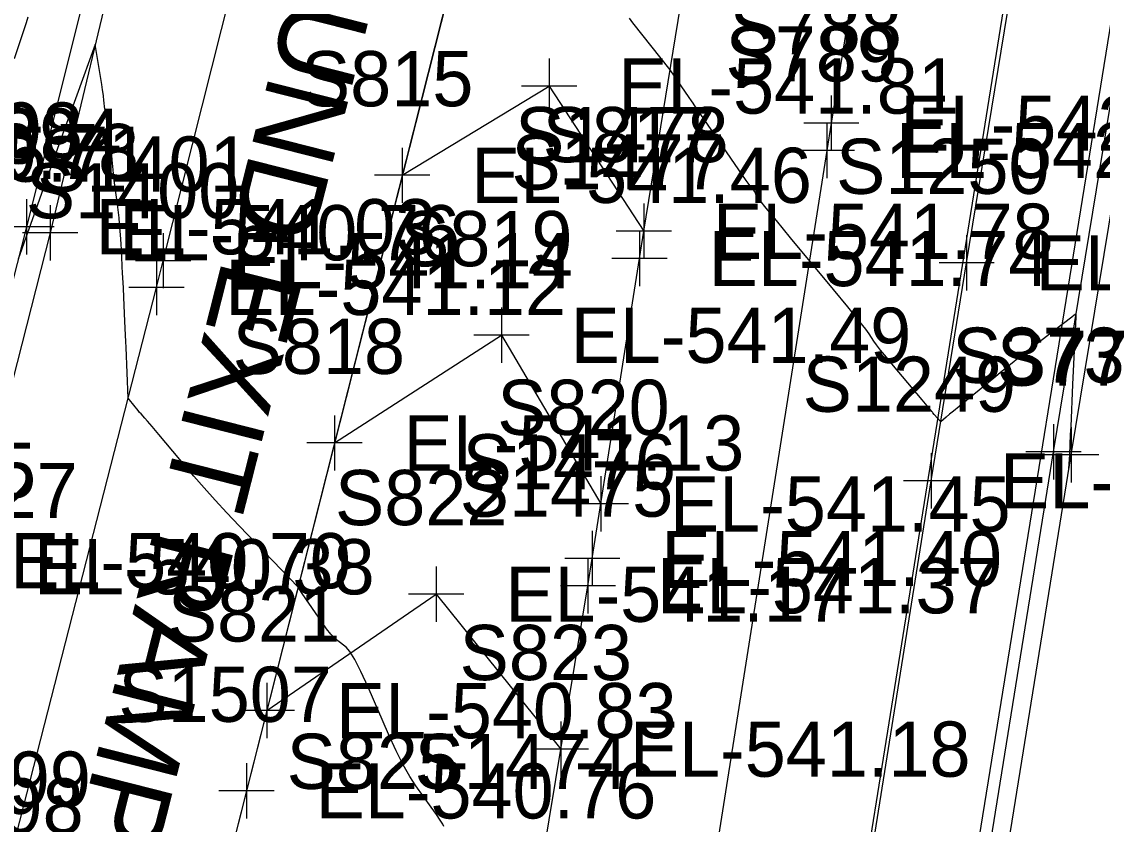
# Model space of a CAD drawing. Extents: x 1724534 to 1727318, y 657156 to 660047.
# Drawn here: x 1725578 to 1725656.3, y 659496.3 to 659554.5 of the extents above; entities that cross this region are included whole.
import ezdxf

# ---------------------------------------------------------------- set-up
doc = ezdxf.new("R2010")
doc.units = 0
for name, color, linetype in [('SURVEY - CENTERLINE - Preliminary', 7, 'Continuous'), ('SURVEY - CONTOURS - Intermediate with optional Text', 7, 'Continuous'), ('SURVEY - DRAINAGE - Area Shapes', 7, 'Continuous'), ('SURVEY - DRAINAGE - Storm Sewer', 7, 'Continuous'), ('SURVEY - DTM - Breaklines', 7, 'Continuous'), ('SURVEY - DTM - Breaklines - Points - Elevations', 7, 'Continuous'), ('SURVEY - DTM - Breaklines - Points - Locators', 7, 'Continuous'), ('SURVEY - DTM - Breaklines - Points - Numbers', 7, 'Continuous'), ('SURVEY - NON-TRANSPORTATION - Features - Points - Elevations', 7, 'Continuous'), ('SURVEY - TRAFFIC CONTROL - Pavement Marking - Points - Elevations', 7, 'Continuous'), ('SURVEY - TRAFFIC CONTROL - Pavement Marking - Points - Locators', 7, 'Continuous'), ('SURVEY - TRAFFIC CONTROL - Pavement Marking - Points - Numbers', 7, 'Continuous'), ('SURVEY - TRAFFIC CONTROL - Pavement Marking with Text', 7, 'Continuous'), ('SURVEY - TRANSPORTATION - Features', 7, 'Continuous'), ('SURVEY - TRANSPORTATION - Features - Points - Elevations', 7, 'Continuous'), ('SURVEY - TRANSPORTATION - Features - Points - Locators', 7, 'Continuous'), ('SURVEY - TRANSPORTATION - Features - Points - Numbers', 7, 'Continuous'), ('SURVEY - TRANSPORTATION - Roads', 7, 'Continuous'), ('SURVEY - TRANSPORTATION - Roads - Points - Elevations', 7, 'Continuous'), ('SURVEY - TRANSPORTATION - Roads - Points - Locators', 7, 'Continuous'), ('SURVEY - TRANSPORTATION - Roads - Points - Numbers', 7, 'Continuous'), ('SURVEY - TRANSPORTATION - Roads Text', 7, 'Continuous')]:
    doc.layers.add(name, color=color, linetype=linetype)

msp = doc.modelspace()

# ---------------------------------------------------------------- linework, layer by layer
at = {"layer": 'SURVEY - CENTERLINE - Preliminary'}
msp.add_line((1725628.749, 659634.745), (1725510.016, 659165.778), dxfattribs=at)
msp.add_line((1725628.749, 659634.745), (1725510.016, 659165.778), dxfattribs=at)
msp.add_line((1725628.749, 659634.745), (1725510.016, 659165.778), dxfattribs=at)
at = {"layer": 'SURVEY - CONTOURS - Intermediate with optional Text'}
for points in [[(1725578.479, 659554.8), (1725578.347, 659554.389), (1725577.489, 659551.776)], [(1725653.9, 659522.09), (1725653.958, 659523.08), (1725654.024, 659524.558), (1725654.049, 659525.135), (1725654.184, 659528.189), (1725654.412, 659533.086), (1725654.423, 659533.317), (1725654.333, 659533.251), (1725654.283, 659533.213), (1725654.275, 659533.207), (1725654.097, 659533.067), (1725652.803, 659532.07), (1725650.992, 659530.675), (1725650.323, 659530.157), (1725649.676, 659529.646), (1725649.051, 659529.144), (1725648.447, 659528.651), (1725645.938, 659526.584), (1725645.53, 659526.251), (1725645.256, 659526.033), (1725645.011, 659525.829), (1725644.607, 659525.485), (1725644.136, 659526.017), (1725644.035, 659526.137), (1725644.01, 659526.171), (1725643.966, 659526.236), (1725643.878, 659526.344), (1725643.276, 659527.064), (1725641.199, 659529.528), (1725640.671, 659530.162), (1725640.257, 659530.671), (1725639.958, 659531.056), (1725639.773, 659531.317), (1725639.433, 659531.849), (1725639.175, 659532.199), (1725638.658, 659532.852), (1725637.881, 659533.806), (1725636.844, 659535.063), (1725633.732, 659538.816), (1725632.706, 659540.057), (1725631.963, 659540.965), (1725631.502, 659541.54), (1725631.324, 659541.782), (1725631.225, 659541.982), (1725631.185, 659542.057), (1725631.138, 659542.133), (1725631.085, 659542.211), (1725631.026, 659542.288), (1725630.859, 659542.497), (1725630.779, 659542.602), (1725630.664, 659542.762), (1725630.513, 659542.976), (1725627.182, 659547.818), (1725626.748, 659548.452), (1725626.665, 659548.576), (1725626.563, 659548.735), (1725626.395, 659548.983), (1725625.008, 659550.977), (1725622.31, 659554.396), (1725622.066, 659554.733)], [(1725608.605, 659496.159), (1725608.527, 659496.337), (1725608.351, 659496.63), (1725608.076, 659497.039), (1725607.702, 659497.564), (1725606.575, 659499.117), (1725606.135, 659499.787), (1725605.661, 659500.632), (1725605.152, 659501.651), (1725604.609, 659502.846), (1725603.116, 659506.264), (1725602.597, 659507.406), (1725602.162, 659508.27), (1725601.809, 659508.855), (1725601.54, 659509.161), (1725600.932, 659509.605), (1725600.69, 659509.814), (1725600.42, 659510.106), (1725600.12, 659510.482), (1725599.792, 659510.942), (1725598.354, 659513.049), (1725598.046, 659513.5), (1725593.771, 659517.948), (1725592.88, 659518.888), (1725592.039, 659519.802), (1725591.248, 659520.69), (1725590.506, 659521.552), (1725587.956, 659524.572), (1725587.469, 659525.145), (1725587.135, 659525.536), (1725586.954, 659525.743), (1725586.675, 659526.051), (1725586.57, 659526.169), (1725586.463, 659526.293), (1725586.355, 659526.423), (1725586.246, 659526.559), (1725585.733, 659527.205), (1725585.592, 659530.859), (1725585.571, 659531.312), (1725585.546, 659531.752), (1725585.501, 659532.764), (1725585.429, 659534.477), (1725585.395, 659535.179), (1725585.329, 659536.264), (1725585.309, 659536.701), (1725585.286, 659537.477), (1725585.276, 659537.714), (1725585.26, 659538.001), (1725585.237, 659538.34), (1725585.207, 659538.73), (1725585.117, 659539.838), (1725585.081, 659540.249), (1725585.04, 659540.65), (1725584.994, 659541.042), (1725584.944, 659541.425), (1725584.803, 659542.432), (1725584.754, 659542.797), (1725584.711, 659543.136), (1725584.676, 659543.449), (1725584.648, 659543.735), (1725584.581, 659544.465), (1725584.55, 659544.77), (1725584.504, 659545.137), (1725584.445, 659545.568), (1725584.373, 659546.061), (1725584.09, 659547.934), (1725584.035, 659548.309), (1725583.998, 659548.583), (1725583.977, 659548.758), (1725583.943, 659549.091), (1725583.921, 659549.265), (1725583.882, 659549.538), (1725583.824, 659549.91), (1725583.351, 659552.807), (1725582.024, 659549.156), (1725580.991, 659546.29), (1725580.237, 659544.206), (1725578.776, 659540.122), (1725578.435, 659539.173), (1725577.779, 659537.276)]]:
    msp.add_lwpolyline(points, dxfattribs=at)
at = {"layer": 'SURVEY - DRAINAGE - Area Shapes'}
msp.add_lwpolyline([(1725457.865, 659006.777), (1725413.857, 659016.262), (1725297.605, 659050.843), (1725314.042, 659296.608), (1725386.76, 659493.901), (1725483.401, 659755.229), (1725623.949, 659732.704), (1725676.22, 659724.326), (1725634.82, 659466.017), (1725543.324, 659353.721), (1725499.683, 659185.923), (1725479.088, 659106.738)], close=True, dxfattribs=at)
at = {"layer": 'SURVEY - DRAINAGE - Storm Sewer'}
msp.add_line((1725684.983, 659727.993), (1725645.113, 659481.278), dxfattribs=at)
at = {"layer": 'SURVEY - DTM - Breaklines'}
for points in [[(1725623.603, 659326.195), (1725625.596, 659340.96), (1725631.474, 659380.353), (1725637.663, 659419.872), (1725643.838, 659459.39), (1725646.925, 659478.842), (1725647.706, 659483.647), (1725654.062, 659523.097), (1725660.549, 659562.561), (1725667.001, 659602.053), (1725673.284, 659641.547), (1725679.659, 659681.01), (1725686.766, 659724.695), (1725687.764, 659730.895), (1725694.149, 659770.379), (1725697.503, 659791.065)], [(1725602.477, 659636.589), (1725597.046, 659612.281), (1725591.056, 659587.95), (1725584.432, 659563.857), (1725578.377, 659539.615), (1725572.193, 659515.421), (1725566.455, 659491.037), (1725562.449, 659475.306), (1725561.076, 659469.841), (1725554.596, 659445.712), (1725548.416, 659421.487), (1725542.14, 659397.279), (1725535.913, 659373.067), (1725529.984, 659349.877), (1725523.806, 659325.59), (1725517.787, 659301.313), (1725511.183, 659275.168), (1725504.884, 659250.966), (1725498.725, 659226.793)]]:
    msp.add_lwpolyline(points, dxfattribs=at)
at = {"layer": 'SURVEY - DTM - Breaklines - Points - Locators'}
for p, q in [((1725578.377, 659541.615), (1725578.377, 659537.615)), ((1725580.377, 659539.615), (1725576.377, 659539.615)), ((1725654.062, 659525.097), (1725654.062, 659521.097)), ((1725656.062, 659523.097), (1725652.062, 659523.097))]:
    msp.add_line(p, q, dxfattribs=at)
at = {"layer": 'SURVEY - TRAFFIC CONTROL - Pavement Marking - Points - Locators'}
for p, q in [((1725616.236, 659551.808), (1725616.236, 659547.808)), ((1725618.236, 659549.808), (1725614.236, 659549.808)), ((1725636.683, 659549.114), (1725636.683, 659545.114)), ((1725638.683, 659547.114), (1725634.683, 659547.114)), ((1725636.368, 659547.139), (1725636.368, 659543.139)), ((1725605.591, 659545.34), (1725605.591, 659541.34)), ((1725638.368, 659545.139), (1725634.368, 659545.139)), ((1725607.591, 659543.34), (1725603.591, 659543.34)), ((1725623.106, 659541.288), (1725623.106, 659537.288)), ((1725625.106, 659539.288), (1725621.106, 659539.288)), ((1725612.791, 659533.753), (1725612.791, 659529.753)), ((1725614.791, 659531.753), (1725610.791, 659531.753)), ((1725600.69, 659525.951), (1725600.69, 659521.951)), ((1725602.69, 659523.951), (1725598.69, 659523.951)), ((1725619.989, 659521.534), (1725619.989, 659517.534)), ((1725621.989, 659519.534), (1725617.989, 659519.534)), ((1725608.06, 659514.995), (1725608.06, 659510.995)), ((1725610.06, 659512.995), (1725606.06, 659512.995)), ((1725595.789, 659506.563), (1725595.789, 659502.563)), ((1725597.789, 659504.563), (1725593.789, 659504.563)), ((1725617.086, 659503.771), (1725617.086, 659499.771)), ((1725619.086, 659501.771), (1725615.086, 659501.771))]:
    msp.add_line(p, q, dxfattribs=at)
at = {"layer": 'SURVEY - TRAFFIC CONTROL - Pavement Marking with Text'}
for points in [[(1725677.077, 659796.306), (1725674.763, 659781.986), (1725662.242, 659705.025), (1725649.129, 659624.102), (1725636.683, 659547.114), (1725636.368, 659545.139), (1725624.177, 659468.103), (1725623.248, 659462.175), (1725617.375, 659424.632), (1725617.069, 659422.656), (1725605.507, 659345.515), (1725605.215, 659343.536), (1725602.951, 659328.104)], [(1725605.591, 659543.34), (1725616.236, 659549.808), (1725623.106, 659539.288)], [(1725600.69, 659523.951), (1725612.791, 659531.753), (1725619.989, 659519.534)], [(1725595.789, 659504.563), (1725608.06, 659512.995), (1725617.086, 659501.771)]]:
    msp.add_lwpolyline(points, dxfattribs=at)
at = {"layer": 'SURVEY - TRANSPORTATION - Features'}
for points in [[(1725622.206, 659326.386), (1725624.286, 659341.139), (1725630.167, 659380.556), (1725636.351, 659420.075), (1725642.552, 659459.59), (1725645.64, 659479.047), (1725646.421, 659483.852), (1725652.777, 659523.307), (1725659.265, 659562.771), (1725665.716, 659602.26), (1725671.999, 659641.754), (1725678.373, 659681.219), (1725685.481, 659724.905), (1725686.48, 659731.104), (1725692.864, 659770.586), (1725696.218, 659791.273)], [(1725603.581, 659636.317), (1725598.147, 659611.998), (1725592.159, 659587.674), (1725585.904, 659563.486), (1725580.094, 659539.18), (1725573.908, 659514.982), (1725567.671, 659490.732), (1725563.666, 659475.001), (1725562.294, 659469.536), (1725556.226, 659445.299), (1725550.205, 659421.034), (1725543.929, 659396.827), (1725537.702, 659372.615), (1725531.77, 659349.415), (1725525.595, 659325.139), (1725519.577, 659300.865), (1725512.973, 659274.714), (1725506.673, 659250.514), (1725500.512, 659226.334)]]:
    msp.add_lwpolyline(points, dxfattribs=at)
at = {"layer": 'SURVEY - TRANSPORTATION - Features - Points - Locators'}
for p, q in [((1725580.094, 659541.18), (1725580.094, 659537.18)), ((1725582.094, 659539.18), (1725578.094, 659539.18)), ((1725652.777, 659525.307), (1725652.777, 659521.307)), ((1725654.777, 659523.307), (1725650.777, 659523.307))]:
    msp.add_line(p, q, dxfattribs=at)
at = {"layer": 'SURVEY - TRANSPORTATION - Roads'}
for points in [[(1725614.209, 659327.48), (1725617.731, 659353.241), (1725618.016, 659355.22), (1725622.921, 659386.843), (1725624.432, 659396.727), (1725627.753, 659418.475), (1725628.057, 659420.452), (1725635.106, 659465.907), (1725635.414, 659467.883), (1725643.908, 659521.207), (1725646.487, 659536.996), (1725655.836, 659594.229), (1725667.285, 659665.297), (1725672.1, 659694.897), (1725680.449, 659746.206), (1725687.947, 659792.609)], [(1725590.712, 659328.916), (1725598.166, 659381.246), (1725598.45, 659383.225), (1725602.437, 659408.918), (1725603.053, 659412.87), (1725607.12, 659438.551), (1725610.58, 659460.277), (1725610.891, 659462.253), (1725615.777, 659493.878), (1725619.05, 659513.608), (1725619.366, 659515.583), (1725622.791, 659537.313), (1725623.106, 659539.288), (1725628.245, 659570.869), (1725628.563, 659572.843), (1725632.342, 659596.54), (1725632.661, 659598.515), (1725636.547, 659622.193)], [(1725509.717, 659226.971), (1725517.054, 659256.051), (1725522.463, 659277.37), (1725530.246, 659308.405), (1725536.116, 659331.674), (1725536.614, 659333.611), (1725542.122, 659354.908), (1725554.364, 659403.386), (1725567.129, 659453.798), (1725567.617, 659455.737), (1725576.381, 659490.656), (1725576.873, 659492.594), (1725587.785, 659535.219), (1725588.276, 659537.157), (1725594.628, 659562.367), (1725602.882, 659595.344), (1725603.37, 659597.283), (1725609.346, 659620.521)], [(1725624.67, 659618.957), (1725609.021, 659556.912), (1725594.317, 659498.747), (1725580.515, 659444.472), (1725570.134, 659403.773), (1725561.33, 659368.865), (1725557.927, 659355.285), (1725547.165, 659312.624), (1725545.206, 659304.869), (1725533.446, 659258.339), (1725527.51, 659235.091)]]:
    msp.add_lwpolyline(points, dxfattribs=at)
at = {"layer": 'SURVEY - TRANSPORTATION - Roads - Points - Locators'}
for p, q in [((1725623.106, 659541.288), (1725623.106, 659537.288)), ((1725588.276, 659539.157), (1725588.276, 659535.157)), ((1725625.106, 659539.288), (1725621.106, 659539.288)), ((1725622.791, 659539.313), (1725622.791, 659535.313)), ((1725646.487, 659538.996), (1725646.487, 659534.996)), ((1725587.785, 659537.219), (1725587.785, 659533.219)), ((1725624.791, 659537.313), (1725620.791, 659537.313)), ((1725590.276, 659537.157), (1725586.276, 659537.157)), ((1725648.487, 659536.996), (1725644.487, 659536.996)), ((1725589.785, 659535.219), (1725585.785, 659535.219)), ((1725643.908, 659523.207), (1725643.908, 659519.207)), ((1725645.908, 659521.207), (1725641.908, 659521.207)), ((1725619.366, 659517.583), (1725619.366, 659513.583)), ((1725621.366, 659515.583), (1725617.366, 659515.583)), ((1725619.05, 659515.608), (1725619.05, 659511.608)), ((1725621.05, 659513.608), (1725617.05, 659513.608)), ((1725594.317, 659500.747), (1725594.317, 659496.747)), ((1725596.317, 659498.747), (1725592.317, 659498.747))]:
    msp.add_line(p, q, dxfattribs=at)

# ---------------------------------------------------------------- texts
at = {"layer": 'SURVEY - DTM - Breaklines - Points - Elevations'}
for s, p in [('EL-570.78', (1725561.845, 659543.065)), ('EL-541.03', (1725583.377, 659537.615)), ('EL-540.70', (1725577.193, 659513.421))]:
    msp.add_text(s, height=4, dxfattribs=at).set_placement(p)
at = {"layer": 'SURVEY - DTM - Breaklines - Points - Numbers'}
for s, p in [('S98', (1725572.946, 659544.615)), ('S77', (1725648.678, 659528.097))]:
    msp.add_text(s, height=4, dxfattribs=at).set_placement(p)
at = {"layer": 'SURVEY - NON-TRANSPORTATION - Features - Points - Elevations'}
for s, p in [('EL-545.71', (1725562.595, 659542.875)), ('EL-544.27', (1725557.4, 659518.505))]:
    msp.add_text(s, height=4, dxfattribs=at).set_placement(p)
at = {"layer": 'SURVEY - TRAFFIC CONTROL - Pavement Marking - Points - Elevations'}
for s, p in [('EL-541.81', (1725621.236, 659547.808)), ('EL-542.20', (1725641.683, 659545.114)), ('EL-542.16', (1725641.368, 659543.139)), ('EL-541.46', (1725610.591, 659541.34)), ('EL-541.78', (1725628.106, 659537.288)), ('EL-541.49', (1725617.791, 659529.753)), ('EL-541.13', (1725605.69, 659521.951)), ('EL-541.45', (1725624.989, 659517.534)), ('EL-541.17', (1725613.06, 659510.995)), ('EL-540.83', (1725600.789, 659502.563)), ('EL-541.18', (1725622.086, 659499.771))]:
    msp.add_text(s, height=4, dxfattribs=at).set_placement(p)
at = {"layer": 'SURVEY - TRAFFIC CONTROL - Pavement Marking - Points - Numbers'}
for s, p in [('S788', (1725629.3, 659552.114)), ('S789', (1725629.016, 659550.139)), ('S815', (1725598.255, 659548.34)), ('S817', (1725615.77, 659544.288)), ('S819', (1725605.439, 659536.753)), ('S818', (1725593.307, 659528.951)), ('S820', (1725612.48, 659524.534)), ('S822', (1725600.724, 659517.995)), ('S821', (1725588.611, 659509.563)), ('S823', (1725609.75, 659506.771)), ('S825', (1725597.221, 659498.888))]:
    msp.add_text(s, height=4, dxfattribs=at).set_placement(p)
at = {"layer": 'SURVEY - TRANSPORTATION - Features - Points - Elevations'}
for s, p in [('EL-540.76', (1725585.094, 659537.18)), ('EL-540.38', (1725578.908, 659512.982))]:
    msp.add_text(s, height=4, dxfattribs=at).set_placement(p)
at = {"layer": 'SURVEY - TRANSPORTATION - Features - Points - Numbers'}
for s, p in [('S394', (1725572.758, 659544.18)), ('S373', (1725645.441, 659528.307)), ('S395', (1725566.572, 659519.982))]:
    msp.add_text(s, height=4, dxfattribs=at).set_placement(p)
at = {"layer": 'SURVEY - TRANSPORTATION - Roads - Points - Elevations'}
for s, p in [('EL-541.78', (1725628.106, 659537.288)), ('EL-541.14', (1725593.276, 659535.157)), ('EL-541.74', (1725627.791, 659535.313)), ('EL-542.23', (1725651.487, 659534.996)), ('EL-541.12', (1725592.785, 659533.219)), ('EL-541.92', (1725648.908, 659519.207)), ('EL-541.40', (1725624.366, 659513.583)), ('EL-541.37', (1725624.05, 659511.608)), ('EL-540.76', (1725599.317, 659496.747))]:
    msp.add_text(s, height=4, dxfattribs=at).set_placement(p)
at = {"layer": 'SURVEY - TRANSPORTATION - Roads - Points - Numbers'}
for s, p in [('S1478', (1725613.771, 659544.288)), ('S1401', (1725579.146, 659542.157)), ('S1477', (1725613.503, 659542.313)), ('S1250', (1725637.026, 659541.996)), ('S1400', (1725578.324, 659540.219)), ('S1249', (1725634.605, 659526.207)), ('S1476', (1725609.968, 659520.583)), ('S1475', (1725609.762, 659518.608)), ('S1507', (1725585.029, 659503.747)), ('S1474', (1725606.489, 659498.878)), ('S1399', (1725567.57, 659497.594)), ('S1398', (1725567.046, 659495.656))]:
    msp.add_text(s, height=4, dxfattribs=at).set_placement(p)
at = {"layer": 'SURVEY - TRANSPORTATION - Roads Text'}
msp.add_text('I-440 EASTBOUND EXIT RAMP (ASP)', height=6, rotation=255.74674, dxfattribs=at).set_placement((1725610.504, 659607.819))

doc.saveas('drawing.dxf')
